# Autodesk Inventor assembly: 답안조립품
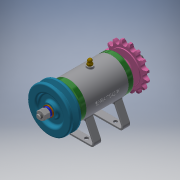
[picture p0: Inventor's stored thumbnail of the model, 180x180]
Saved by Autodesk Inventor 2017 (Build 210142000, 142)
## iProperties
Part Number: 답안조립품
Material: 일반
Document SubType Name: Assembly
Designer: Administrator
Author: Administrator
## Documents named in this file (16)
- C:\Users\Administrator\Desktop\711206V1023\답안조립품.iam
- C:\Users\Administrator\Desktop\711206V1023\본체.ipt
- C:\Users\Administrator\Desktop\711206V1023\커버.ipt
- C:\Users\Administrator\Desktop\711206V1023\베어링 6002.ipt
- C:\Users\Administrator\Desktop\711206V1023\축.ipt
- C:\Users\Administrator\Desktop\711206V1023\오일 실 15 x 25 x 7.ipt
- C:\Users\Administrator\Desktop\711206V1023\볼트 M4 x 12.ipt
- C:\Users\Administrator\Desktop\711206V1023\키 3 x 3.ipt
- C:\Users\Administrator\Desktop\711206V1023\V벨트풀리.ipt
- C:\Users\Administrator\Desktop\711206V1023\스프로킷.ipt
- C:\Users\Administrator\Desktop\711206V1023\와셔 8 x 17.ipt
- C:\Users\Administrator\Desktop\711206V1023\스프링와셔 8.ipt
- C:\Users\Administrator\Desktop\711206V1023\너트 M8.ipt
- C:\Users\Administrator\Desktop\711206V1023\와셔 6 x 11.5.ipt
- C:\Users\Administrator\Desktop\711206V1023\볼트 M6 x 8.ipt
- C:\Users\Administrator\Desktop\711206V1023\니플 M6 x 0.75.ipt
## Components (11 placed, 3 different names)
1. KS B 2023 6002 - 15 x 32 x 9:1
2. KS B 2023 6002 - 15 x 32 x 9:2
3. ISO 4762 M4 x 12:1
4. ISO 4762 M4 x 12:2
5. ISO 4762 M4 x 12:3
6. ISO 4762 M4 x 12:4
7. ISO 4762 M4 x 12:5
8. ISO 4762 M4 x 12:6
9. ISO 4762 M4 x 12:7
10. ISO 4762 M4 x 12:8
11. V벨트풀리:1
